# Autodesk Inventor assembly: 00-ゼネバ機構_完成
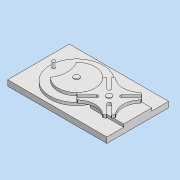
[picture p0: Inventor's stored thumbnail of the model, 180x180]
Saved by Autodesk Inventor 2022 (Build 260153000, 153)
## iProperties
Created: 2021-07
Part Number: 00-ゼネバ機構_完成
Document SubType Name: Assembly
Designer: DesignLab
Author: DesignLab
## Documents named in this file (5)
- d:\Users\DesignLab\Desktop\ver2022\ch04\00-ゼネバ機構_完成.iam
- d:\Users\DesignLab\Desktop\ver2022\ch04\03-ベース板_完成.ipt
- d:\Users\DesignLab\Desktop\ver2022\ch04\01-駆動車_完成.ipt
- d:\Users\DesignLab\Desktop\ver2022\ch04\02-従動車_完成.ipt
- d:\Users\DesignLab\Desktop\ver2022\ch04\04-ピン_完成.ipt
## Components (5 placed, 4 different names)
1. 03-ベース板_完成:1 — 回転:1, 回転:2, 駆動車回転
2. 01-駆動車_完成:1 — 回転:1, フラッシュ:1, 駆動車回転
3. 02-従動車_完成:1 — 回転:2, 回転:3
4. 04-ピン_完成:1 — フラッシュ:1
5. 04-ピン_完成:2 — 回転:3
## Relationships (5: RevoluteJoint 3, Flush 1, Angle 1)
- 回転:1 [RevoluteJoint]: 03-ベース板_完成:1 ↔ 01-駆動車_完成:1
- 回転:2 [RevoluteJoint]: 03-ベース板_完成:1 ↔ 02-従動車_完成:1
- フラッシュ:1 [Flush]: 01-駆動車_完成:1 ↔ 04-ピン_完成:1
- 回転:3 [RevoluteJoint]: 02-従動車_完成:1 ↔ 04-ピン_完成:2
- 駆動車回転 [Angle]: 03-ベース板_完成:1 ↔ 01-駆動車_完成:1
